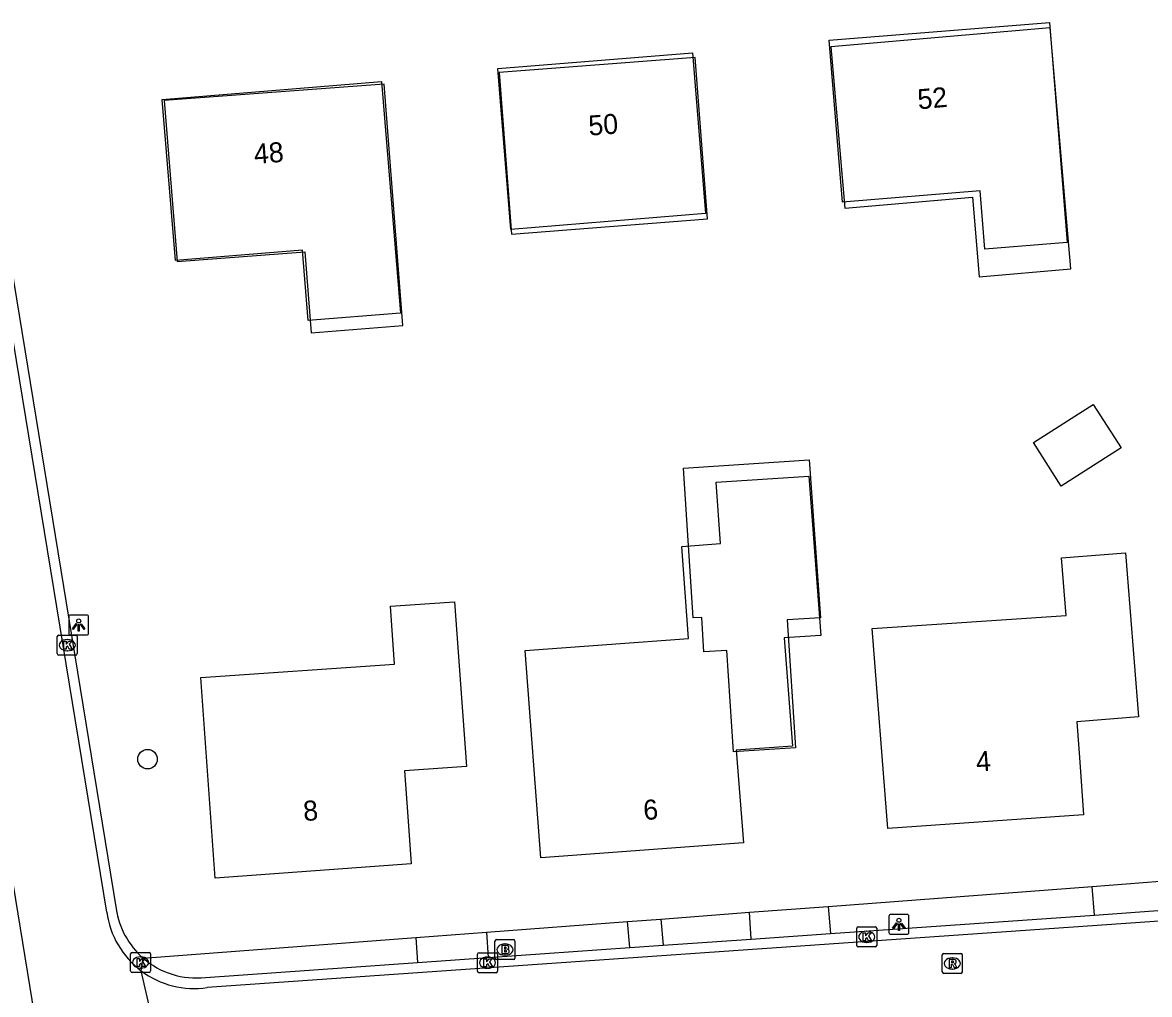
# Model space of a CAD drawing. Extents: x 162675 to 163482, y 379761 to 381227.
# Drawn here: x 163053.2 to 163109.5, y 380399.9 to 380448.5 of the extents above; entities that cross this region are included whole.
import ezdxf

# ---------------------------------------------------------------- set-up
doc = ezdxf.new("R2010")
doc.units = 0
for name, color, linetype in [('IMGEO_Boom', 7, 'Continuous'), ('IMGEO_Brandkraan', 7, 'Continuous'), ('IMGEO_Groenvoorziening', 7, 'Continuous'), ('IMGEO_Kolk', 7, 'Continuous'), ('IMGEO_Lichtpunt', 7, 'Continuous'), ('IMGEO_Pand', 7, 'Continuous'), ('IMGEO_Pand_nummerreeks', 7, 'Continuous'), ('IMGEO_Pand_vergunning_verleend', 7, 'Continuous'), ('IMGEO_Rijbaan_lokaal_gesloten', 7, 'Continuous'), ('IMGEO_Rijbaan_lokaal_open', 7, 'Continuous'), ('IMGEO_Rioolput', 7, 'Continuous'), ('IMGEO_Voetpad_halfverhard', 7, 'Continuous'), ('IMGEO_Voetpad_open', 7, 'Continuous')]:
    doc.layers.add(name, color=color, linetype=linetype)

msp = doc.modelspace()

# ---------------------------------------------------------------- linework, layer by layer
at = {"layer": 'IMGEO_Boom'}
msp.add_circle((163059.42, 380411.622), 0.489, dxfattribs=at)
at = {"layer": 'IMGEO_Brandkraan'}
for p, q in [((163076.785, 380401.673), (163076.785, 380402.525)), ((163076.86, 380402.599), (163077.712, 380402.599)), ((163077.273, 380402.379), (163077.298, 380402.379)), ((163077.786, 380402.525), (163077.786, 380401.673)), ((163077.296, 380401.819), (163077.271, 380401.819)), ((163077.712, 380401.599), (163076.86, 380401.599))]:
    msp.add_line(p, q, dxfattribs=at)
for points in [[(163076.785, 380401.673), (163076.785, 380402.525)], [(163076.86, 380402.599), (163077.712, 380402.599)], [(163077.133, 380402.299), (163077.133, 380401.899), (163077.346, 380401.899)], [(163077.364, 380402.299), (163077.133, 380402.299)], [(163077.786, 380402.525), (163077.786, 380401.673)], [(163077.312, 380402.218), (163077.258, 380402.218), (163077.258, 380402.142)], [(163077.258, 380402.142), (163077.311, 380402.142)], [(163077.32, 380402.066), (163077.258, 380402.066), (163077.258, 380401.985)], [(163077.258, 380401.985), (163077.32, 380401.985)], [(163077.712, 380401.599), (163076.86, 380401.599)]]:
    msp.add_lwpolyline(points, dxfattribs=at)
for centre, radius, start, end in [((163076.862, 380402.523), 0.0765, 91.552, 178.448), ((163076.862, 380402.523), 0.0765, 91.552, 178.448), ((163077.368, 380402.154), 0.145, 59.4692, 91.5367), ((163077.71, 380402.523), 0.0765, 1.552, 88.448), ((163077.71, 380402.523), 0.0765, 1.552, 88.448), ((163077.313, 380402.18), 0.0379, 267.8285, 90.9355), ((163077.321, 380402.025), 0.0404, 269.8759, 90.5077), ((163077.352, 380402.15), 0.251, 268.6676, 293.5347), ((163077.393, 380402.201), 0.0922, 285.5137, 58.1501), ((163077.398, 380402.009), 0.105, 301.3115, 78.989), ((163076.862, 380401.675), 0.0765, 181.552, 268.448), ((163076.862, 380401.675), 0.0765, 181.552, 268.448), ((163077.71, 380401.675), 0.0765, 271.552, 358.448), ((163077.71, 380401.675), 0.0765, 271.552, 358.448)]:
    msp.add_arc(centre, radius, start, end, dxfattribs=at)
for centre, major_axis, ratio, start_param, end_param in [((163077.272, 380402.099), (-0.387, 0.002), 0.722429, 4.712389, 7.853982), ((163077.297, 380402.099), (-0.39, 0.002), 0.717154, 1.570796, 4.712389)]:
    msp.add_ellipse(centre, major_axis=major_axis, ratio=ratio, start_param=start_param, end_param=end_param, dxfattribs=at)
at = {"layer": 'IMGEO_Groenvoorziening'}
for points in [[(163093.438, 380404.26), (163106.644, 380405.259)], [(163076.355, 380402.967), (163083.412, 380403.501)], [(163085.079, 380403.627), (163089.515, 380403.963)], [(163059.202, 380401.669), (163072.831, 380402.7)]]:
    msp.add_lwpolyline(points, dxfattribs=at)
at = {"layer": 'IMGEO_Kolk'}
for p, q in [((163054.909, 380416.899), (163054.909, 380417.751)), ((163054.984, 380417.825), (163055.836, 380417.825)), ((163055.397, 380417.605), (163055.422, 380417.605)), ((163055.91, 380417.751), (163055.91, 380416.899)), ((163055.42, 380417.045), (163055.395, 380417.045)), ((163055.836, 380416.825), (163054.984, 380416.825)), ((163094.867, 380402.309), (163094.867, 380403.161)), ((163094.942, 380403.235), (163095.794, 380403.235)), ((163095.355, 380403.015), (163095.38, 380403.015)), ((163095.868, 380403.161), (163095.868, 380402.309)), ((163095.378, 380402.455), (163095.353, 380402.455)), ((163058.573, 380401.027), (163058.573, 380401.879)), ((163058.648, 380401.953), (163059.5, 380401.953)), ((163059.061, 380401.733), (163059.086, 380401.733)), ((163059.574, 380401.879), (163059.574, 380401.027)), ((163075.914, 380401.015), (163075.914, 380401.867)), ((163075.989, 380401.941), (163076.841, 380401.941)), ((163076.915, 380401.867), (163076.915, 380401.015)), ((163095.794, 380402.235), (163094.942, 380402.235)), ((163059.084, 380401.173), (163059.059, 380401.173)), ((163076.402, 380401.721), (163076.427, 380401.721)), ((163059.5, 380400.953), (163058.648, 380400.953)), ((163076.841, 380400.941), (163075.989, 380400.941)), ((163076.425, 380401.161), (163076.4, 380401.161))]:
    msp.add_line(p, q, dxfattribs=at)
for points in [[(163054.909, 380416.899), (163054.909, 380417.751)], [(163054.984, 380417.825), (163055.836, 380417.825)], [(163055.23, 380417.525), (163055.353, 380417.525), (163055.353, 380417.374), (163055.483, 380417.525), (163055.647, 380417.525), (163055.501, 380417.374), (163055.654, 380417.125), (163055.502, 380417.125), (163055.417, 380417.289), (163055.353, 380417.222), (163055.353, 380417.125), (163055.23, 380417.125), (163055.23, 380417.525)], [(163055.91, 380417.751), (163055.91, 380416.899)], [(163055.836, 380416.825), (163054.984, 380416.825)], [(163094.867, 380402.309), (163094.867, 380403.161)], [(163094.942, 380403.235), (163095.794, 380403.235)], [(163095.188, 380402.935), (163095.311, 380402.935), (163095.311, 380402.784), (163095.441, 380402.935), (163095.605, 380402.935), (163095.459, 380402.784), (163095.612, 380402.535), (163095.46, 380402.535), (163095.375, 380402.699), (163095.311, 380402.632), (163095.311, 380402.535), (163095.188, 380402.535), (163095.188, 380402.935)], [(163095.868, 380403.161), (163095.868, 380402.309)], [(163058.573, 380401.027), (163058.573, 380401.879)], [(163058.648, 380401.953), (163059.5, 380401.953)], [(163059.574, 380401.879), (163059.574, 380401.027)], [(163075.914, 380401.015), (163075.914, 380401.867)], [(163075.989, 380401.941), (163076.841, 380401.941)], [(163076.915, 380401.867), (163076.915, 380401.015)], [(163095.794, 380402.235), (163094.942, 380402.235)], [(163058.894, 380401.653), (163059.017, 380401.653), (163059.017, 380401.502), (163059.147, 380401.653), (163059.311, 380401.653), (163059.165, 380401.502), (163059.318, 380401.253), (163059.166, 380401.253), (163059.081, 380401.417), (163059.017, 380401.35), (163059.017, 380401.253), (163058.894, 380401.253), (163058.894, 380401.653)], [(163076.235, 380401.641), (163076.358, 380401.641), (163076.358, 380401.49), (163076.488, 380401.641), (163076.652, 380401.641), (163076.506, 380401.49), (163076.659, 380401.241), (163076.507, 380401.241), (163076.422, 380401.405), (163076.358, 380401.338), (163076.358, 380401.241), (163076.235, 380401.241), (163076.235, 380401.641)], [(163059.5, 380400.953), (163058.648, 380400.953)], [(163076.841, 380400.941), (163075.989, 380400.941)]]:
    msp.add_lwpolyline(points, dxfattribs=at)
for centre, start, end in [((163054.986, 380417.749), 91.552, 178.448), ((163054.986, 380417.749), 91.552, 178.448), ((163055.834, 380417.749), 1.552, 88.448), ((163055.834, 380417.749), 1.552, 88.448), ((163054.986, 380416.901), 181.552, 268.448), ((163054.986, 380416.901), 181.552, 268.448), ((163055.834, 380416.901), 271.552, 358.448), ((163055.834, 380416.901), 271.552, 358.448), ((163094.944, 380403.159), 91.552, 178.448), ((163094.944, 380403.159), 91.552, 178.448), ((163095.792, 380403.159), 1.552, 88.448), ((163095.792, 380403.159), 1.552, 88.448), ((163094.944, 380402.311), 181.552, 268.448), ((163094.944, 380402.311), 181.552, 268.448), ((163095.792, 380402.311), 271.552, 358.448), ((163095.792, 380402.311), 271.552, 358.448), ((163058.65, 380401.877), 91.552, 178.448), ((163058.65, 380401.877), 91.552, 178.448), ((163059.498, 380401.877), 1.552, 88.448), ((163059.498, 380401.877), 1.552, 88.448), ((163075.991, 380401.865), 91.552, 178.448), ((163075.991, 380401.865), 91.552, 178.448), ((163076.839, 380401.865), 1.552, 88.448), ((163076.839, 380401.865), 1.552, 88.448), ((163058.65, 380401.029), 181.552, 268.448), ((163058.65, 380401.029), 181.552, 268.448), ((163059.498, 380401.029), 271.552, 358.448), ((163059.498, 380401.029), 271.552, 358.448), ((163075.991, 380401.017), 181.552, 268.448), ((163075.991, 380401.017), 181.552, 268.448), ((163076.839, 380401.017), 271.552, 358.448), ((163076.839, 380401.017), 271.552, 358.448)]:
    msp.add_arc(centre, 0.0765, start, end, dxfattribs=at)
for centre, major_axis, ratio, start_param, end_param in [((163055.396, 380417.325), (-0.387, 0.002), 0.722429, 4.712389, 7.853982), ((163055.421, 380417.325), (-0.39, 0.002), 0.717154, 1.570796, 4.712389), ((163095.354, 380402.735), (-0.387, 0.002), 0.722429, 4.712389, 7.853982), ((163095.379, 380402.735), (-0.39, 0.002), 0.717154, 1.570796, 4.712389), ((163059.06, 380401.453), (-0.387, 0.002), 0.722429, 4.712389, 7.853982), ((163059.085, 380401.453), (-0.39, 0.002), 0.717154, 1.570796, 4.712389), ((163076.401, 380401.441), (-0.387, 0.002), 0.722429, 4.712389, 7.853982), ((163076.426, 380401.441), (-0.39, 0.002), 0.717154, 1.570796, 4.712389)]:
    msp.add_ellipse(centre, major_axis=major_axis, ratio=ratio, start_param=start_param, end_param=end_param, dxfattribs=at)
at = {"layer": 'IMGEO_Lichtpunt'}
for p, q in [((163055.48, 380418.736), (163055.48, 380417.929)), ((163055.48, 380418.736), (163055.48, 380417.929)), ((163056.382, 380418.831), (163055.574, 380418.831)), ((163056.382, 380418.831), (163055.574, 380418.831)), ((163056.476, 380417.929), (163056.476, 380418.736)), ((163056.476, 380417.929), (163056.476, 380418.736)), ((163055.574, 380417.835), (163056.382, 380417.835)), ((163055.574, 380417.835), (163056.382, 380417.835)), ((163096.475, 380403.764), (163096.475, 380402.957)), ((163096.475, 380403.764), (163096.475, 380402.957)), ((163097.377, 380403.859), (163096.569, 380403.859)), ((163097.377, 380403.859), (163096.569, 380403.859)), ((163097.471, 380402.957), (163097.471, 380403.764)), ((163097.471, 380402.957), (163097.471, 380403.764)), ((163096.569, 380402.863), (163097.377, 380402.863)), ((163096.569, 380402.863), (163097.377, 380402.863))]:
    msp.add_line(p, q, dxfattribs=at)
for points in [[(163055.854, 380418.4), (163055.893, 380418.372), (163055.705, 380418.11), (163055.667, 380418.137), (163055.854, 380418.4)], [(163055.956, 380418.352), (163056.003, 380418.352), (163056.003, 380418.03), (163055.956, 380418.03), (163055.956, 380418.352)], [(163056.066, 380418.372), (163056.104, 380418.399), (163056.291, 380418.137), (163056.252, 380418.109), (163056.066, 380418.372)], [(163096.849, 380403.428), (163096.888, 380403.4), (163096.7, 380403.138), (163096.662, 380403.165), (163096.849, 380403.428)], [(163097.061, 380403.4), (163097.099, 380403.427), (163097.286, 380403.165), (163097.247, 380403.137), (163097.061, 380403.4)], [(163096.951, 380403.38), (163096.998, 380403.38), (163096.998, 380403.058), (163096.951, 380403.058), (163096.951, 380403.38)]]:
    msp.add_lwpolyline(points, dxfattribs=at)
for centre in [(163055.979, 380418.534), (163096.974, 380403.562)]:
    msp.add_circle(centre, 0.0994, dxfattribs=at)
for centre, start, end in [((163055.574, 380418.736), 90, 180), ((163055.574, 380418.736), 90, 180), ((163056.382, 380418.736), 0, 90), ((163056.382, 380418.736), 0, 90), ((163055.574, 380417.929), 180, 270), ((163055.574, 380417.929), 180, 270), ((163056.382, 380417.929), 270, 0), ((163056.382, 380417.929), 270, 360), ((163096.569, 380403.764), 90, 180), ((163096.569, 380403.764), 90, 180), ((163097.377, 380403.764), 0, 90), ((163097.377, 380403.764), 0, 90), ((163096.569, 380402.957), 180, 270), ((163096.569, 380402.957), 180, 270), ((163097.377, 380402.957), 270, 0), ((163097.377, 380402.957), 270, 360)]:
    msp.add_arc(centre, 0.0946, start, end, dxfattribs=at)
at = {"layer": 'IMGEO_Pand'}
for points in [[(163104.532, 380448.207), (163093.568, 380447.254), (163094.268, 380439.176), (163100.649, 380439.728), (163100.994, 380435.745), (163105.577, 380436.142), (163104.532, 380448.207)], [(163086.789, 380446.724), (163076.997, 380445.97), (163077.619, 380437.885), (163087.411, 380438.639), (163086.789, 380446.724)], [(163071.245, 380445.386), (163060.254, 380444.565), (163060.897, 380436.505), (163067.285, 380437.003), (163067.601, 380432.95), (163072.187, 380433.307), (163071.245, 380445.386)], [(163103.697, 380427.459), (163106.688, 380429.367), (163108.078, 380427.19), (163105.086, 380425.282), (163103.697, 380427.459)], [(163092.478, 380425.772), (163093.067, 380417.806), (163091.248, 380417.686), (163091.653, 380412.276), (163088.849, 380412.077), (163089.214, 380407.436), (163079.07, 380406.684), (163078.301, 380417.055), (163086.46, 380417.66), (163086.119, 380422.265), (163088.065, 380422.409), (163087.837, 380425.477), (163092.478, 380425.772)], [(163105.342, 380418.802), (163105.11, 380421.693), (163108.3, 380421.949), (163108.958, 380413.735), (163105.875, 380413.488), (163106.017, 380411.469), (163106.202, 380408.845), (163096.42, 380408.157), (163095.643, 380418.157), (163105.342, 380418.802)], [(163075.36, 380411.262), (163072.267, 380411.044), (163072.429, 380408.756), (163072.593, 380406.394), (163062.792, 380405.667), (163062.082, 380415.705), (163071.765, 380416.368), (163071.563, 380419.271), (163074.758, 380419.493), (163075.36, 380411.262)]]:
    msp.add_lwpolyline(points, dxfattribs=at)
at = {"layer": 'IMGEO_Pand_vergunning_verleend'}
for points in [[(163093.498, 380447.577), (163104.498, 380448.466), (163105.387, 380437.465), (163101.266, 380437.132), (163101.031, 380440.044), (163094.152, 380439.488), (163093.498, 380447.577)], [(163076.926, 380446.159), (163086.652, 380446.951), (163087.307, 380438.915), (163077.581, 380438.122), (163076.926, 380446.159)], [(163060.154, 380444.611), (163071.122, 380445.508), (163072.069, 380433.934), (163067.446, 380433.556), (163067.158, 380437.08), (163060.813, 380436.561), (163060.154, 380444.611)], [(163092.492, 380426.586), (163093.052, 380418.693), (163091.387, 380418.586), (163091.799, 380412.181), (163088.704, 380411.982), (163088.377, 380417.064), (163087.231, 380416.99), (163087.12, 380418.714), (163086.688, 380418.686), (163086.206, 380426.181), (163092.492, 380426.586)]]:
    msp.add_lwpolyline(points, dxfattribs=at)
at = {"layer": 'IMGEO_Rijbaan_lokaal_gesloten'}
for points in [[(163057.38, 380403.975), (163052.079, 380436.342)], [(163048.058, 380433.778), (163059.565, 380363.138)], [(163126.503, 380404.662), (163062.407, 380400.199)], [(163060.816, 380393.582), (163059.103, 380401.035)]]:
    msp.add_lwpolyline(points, dxfattribs=at)
for centre, radius, start, end in [((163061.751, 380404.562), 4.41, 187.6462, 233.099), ((163061.753, 380404.561), 4.411, 233.0742, 278.5271)]:
    msp.add_arc(centre, radius, start, end, dxfattribs=at)
at = {"layer": 'IMGEO_Rijbaan_lokaal_open'}
for points in [[(163052.595, 380436.378), (163057.855, 380404.14)], [(163106.745, 380403.824), (163110.143, 380404.063)], [(163093.564, 380402.898), (163106.745, 380403.824)], [(163089.584, 380402.619), (163093.564, 380402.898)], [(163083.53, 380402.194), (163085.196, 380402.311)], [(163085.196, 380402.311), (163089.584, 380402.619)], [(163076.444, 380401.696), (163083.53, 380402.194)], [(163059.103, 380401.035), (163059.202, 380401.669)], [(163062.309, 380400.703), (163072.919, 380401.448)], [(163072.919, 380401.448), (163076.444, 380401.696)]]:
    msp.add_lwpolyline(points, dxfattribs=at)
for centre, radius, start, end in [((163061.865, 380404.723), 4.052, 188.2771, 228.9146), ((163061.856, 380404.724), 4.046, 229.0231, 276.4348)]:
    msp.add_arc(centre, radius, start, end, dxfattribs=at)
at = {"layer": 'IMGEO_Rioolput'}
for p, q in [((163099.145, 380400.98), (163099.145, 380401.832)), ((163099.22, 380401.906), (163100.072, 380401.906)), ((163100.146, 380401.832), (163100.146, 380400.98)), ((163099.633, 380401.686), (163099.658, 380401.686)), ((163100.072, 380400.906), (163099.22, 380400.906)), ((163099.656, 380401.126), (163099.631, 380401.126))]:
    msp.add_line(p, q, dxfattribs=at)
for points in [[(163099.145, 380400.98), (163099.145, 380401.832)], [(163099.22, 380401.906), (163100.072, 380401.906)], [(163100.146, 380401.832), (163100.146, 380400.98)], [(163099.734, 380401.604), (163099.482, 380401.606), (163099.482, 380401.206)], [(163099.482, 380401.206), (163099.606, 380401.206), (163099.606, 380401.368), (163099.617, 380401.368)], [(163099.66, 380401.525), (163099.606, 380401.525), (163099.606, 380401.444)], [(163099.606, 380401.444), (163099.658, 380401.444)], [(163099.664, 380401.339), (163099.735, 380401.206), (163099.875, 380401.206), (163099.81, 380401.332)], [(163100.072, 380400.906), (163099.22, 380400.906)]]:
    msp.add_lwpolyline(points, dxfattribs=at)
for centre, radius, start, end in [((163099.222, 380401.83), 0.0765, 91.552, 178.448), ((163099.222, 380401.83), 0.0765, 91.552, 178.448), ((163100.07, 380401.83), 0.0765, 1.552, 88.448), ((163100.07, 380401.83), 0.0765, 1.552, 88.448), ((163099.616, 380401.315), 0.0533, 26.0293, 88.6989), ((163099.642, 380401.633), 0.19, 274.7715, 282.9687), ((163099.666, 380401.429), 0.0964, 77.0061, 93.1865), ((163099.68, 380401.486), 0.0378, 276.6634, 79.6772), ((163099.733, 380401.494), 0.109, 350.3612, 89.416), ((163099.731, 380401.494), 0.112, 277.5842, 350.9817), ((163099.715, 380401.279), 0.108, 29.5134, 73.7905), ((163099.222, 380400.982), 0.0765, 181.552, 268.448), ((163099.222, 380400.982), 0.0765, 181.552, 268.448), ((163100.07, 380400.982), 0.0765, 271.552, 358.448), ((163100.07, 380400.982), 0.0765, 271.552, 358.448)]:
    msp.add_arc(centre, radius, start, end, dxfattribs=at)
for centre, major_axis, ratio, start_param, end_param in [((163099.632, 380401.406), (-0.387, 0.002), 0.722429, 4.712389, 7.853982), ((163099.657, 380401.406), (-0.39, 0.002), 0.717154, 1.570796, 4.712389)]:
    msp.add_ellipse(centre, major_axis=major_axis, ratio=ratio, start_param=start_param, end_param=end_param, dxfattribs=at)
at = {"layer": 'IMGEO_Voetpad_halfverhard'}
for points in [[(163089.515, 380403.963), (163093.438, 380404.26)], [(163093.438, 380404.26), (163093.564, 380402.898)], [(163089.584, 380402.619), (163089.515, 380403.963)]]:
    msp.add_lwpolyline(points, dxfattribs=at)
at = {"layer": 'IMGEO_Voetpad_open'}
for points in [[(163106.644, 380405.259), (163110.041, 380405.516)], [(163106.745, 380403.824), (163106.644, 380405.259)], [(163083.412, 380403.501), (163085.079, 380403.627)], [(163083.53, 380402.194), (163083.412, 380403.501)], [(163085.079, 380403.627), (163085.196, 380402.311)], [(163072.831, 380402.7), (163076.355, 380402.967)], [(163076.355, 380402.967), (163076.444, 380401.696)], [(163072.831, 380402.7), (163072.919, 380401.448)]]:
    msp.add_lwpolyline(points, dxfattribs=at)

# ---------------------------------------------------------------- texts
at = {"layer": 'IMGEO_Pand_nummerreeks'}
for s, rotation, p in [('52', 4.9675, (163097.95, 380444.122)), ('50', 4.4003, (163081.493, 380442.806)), ('48', 4.2743, (163064.772, 380441.392)), ('4', 4.0232, (163100.86, 380410.996)), ('6', 4.2399, (163084.233, 380408.571)), ('8', 4.2422, (163067.235, 380408.524))]:
    msp.add_text(s, height=1, rotation=rotation, dxfattribs=at).set_placement(p)

doc.saveas('drawing.dxf')
